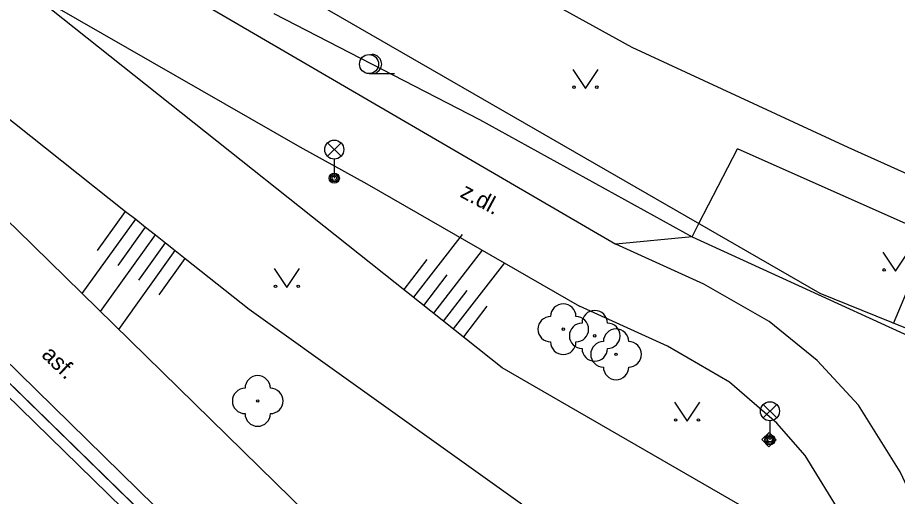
# Model space of a CAD drawing. Extents: x -598932 to -598196, y -1162207 to -1161504.
# Drawn here: x -598623.8 to -598589.11, y -1162050.68 to -1162031.8 of the extents above; entities that cross this region are included whole.
import ezdxf

# ---------------------------------------------------------------- set-up
doc = ezdxf.new("R2010")
doc.units = 0
for name, color, linetype in [('Level 22', 7, 'Continuous'), ('Level 33', 7, 'Continuous'), ('Level 36', 7, 'Continuous'), ('specificka linie pasportu komunikaci', 7, 'Continuous'), ('TM - chodniky - VP', 7, 'Continuous'), ('TM - hladina vodniho toku_ bazenu_ nadrze', 7, 'Continuous'), ('TM - horni hrana svahu', 7, 'Continuous'), ('TM - popis povrchu', 7, 'Continuous'), ('TM - rozhrani ploch obecne - VP', 7, 'Continuous'), ('TM - srafovani', 7, 'Continuous'), ('TM - zabradli - VP', 7, 'Continuous')]:
    doc.layers.add(name, color=color, linetype=linetype)

msp = doc.modelspace()

# ---------------------------------------------------------------- linework, layer by layer
at = {"layer": 'Level 22'}
for centre in [(-598602.28, -1162044.09), (-598601.04, -1162044.35), (-598600.2, -1162045.08), (-598614.33, -1162046.92)]:
    msp.add_circle(centre, 0.05, dxfattribs=at)
for centre, start, end in [((-598602.28, -1162043.59), 0, 180), ((-598601.04, -1162043.85), 0, 180), ((-598602.78, -1162044.09), 90, 270), ((-598601.78, -1162044.09), 270, 90), ((-598601.54, -1162044.35), 90, 270), ((-598600.2, -1162044.58), 0, 180), ((-598600.54, -1162044.35), 270, 90), ((-598602.28, -1162044.59), 180, 0), ((-598600.7, -1162045.08), 90, 270), ((-598599.7, -1162045.08), 270, 90), ((-598601.04, -1162044.85), 180, 0), ((-598600.2, -1162045.58), 180, 0), ((-598614.33, -1162046.42), 0, 180), ((-598614.83, -1162046.92), 90, 270), ((-598613.83, -1162046.92), 270, 90), ((-598614.33, -1162047.42), 180, 0)]:
    msp.add_arc(centre, 0.5, start, end, dxfattribs=at)
at = {"layer": 'Level 33'}
for p, q in [((-598611.575, -1162037.27), (-598611.045, -1162036.74)), ((-598611.575, -1162036.74), (-598611.045, -1162037.27)), ((-598611.31, -1162037.38), (-598611.31, -1162038.13)), ((-598594.395, -1162047.59), (-598593.865, -1162047.06)), ((-598594.395, -1162047.06), (-598593.865, -1162047.59)), ((-598594.13, -1162047.7), (-598594.13, -1162048.45))]:
    msp.add_line(p, q, dxfattribs=at)
for centre, radius in [((-598611.31, -1162037.005), 0.375), ((-598611.31, -1162038.13), 0.2), ((-598611.31, -1162038.13), 0.145), ((-598611.31, -1162038.13), 0.0876), ((-598594.13, -1162047.325), 0.375), ((-598594.13, -1162048.45), 0.2), ((-598594.13, -1162048.45), 0.145), ((-598594.13, -1162048.45), 0.0876)]:
    msp.add_circle(centre, radius, dxfattribs=at)
at = {"layer": 'Level 36'}
msp.add_line((-598609.94, -1162034.005), (-598608.94, -1162034.005), dxfattribs=at)
for points in [[(-598601.91, -1162033.84), (-598601.41, -1162034.59), (-598600.91, -1162033.84)], [(-598589.68, -1162041.05), (-598589.18, -1162041.8), (-598588.68, -1162041.05)], [(-598613.68, -1162041.7), (-598613.18, -1162042.45), (-598612.68, -1162041.7)], [(-598597.9, -1162046.97), (-598597.4, -1162047.72), (-598596.9, -1162046.97)]]:
    msp.add_lwpolyline(points, dxfattribs=at)
for centre, radius in [((-598609.94, -1162033.63), 0.375), ((-598601.86, -1162034.54), 0.05), ((-598600.961, -1162034.54), 0.05), ((-598589.63, -1162041.75), 0.05), ((-598613.63, -1162042.4), 0.05), ((-598612.731, -1162042.4), 0.05), ((-598597.85, -1162047.67), 0.05), ((-598596.951, -1162047.67), 0.05)]:
    msp.add_circle(centre, radius, dxfattribs=at)
msp.add_arc((-598609.815, -1162033.63), 0.375, 260.4059, 99.5941, dxfattribs=at)
at = {"layer": 'specificka linie pasportu komunikaci'}
for points in [[(-598613.699, -1162031.635), (-598613.693, -1162031.639), (-598605.587, -1162035.812), (-598597.2, -1162040.447)], [(-598598.18, -1162071.56), (-598600.34, -1162069.418), (-598614.157, -1162055.953), (-598633.82, -1162036.75)], [(-598597.2, -1162040.447), (-598596.929, -1162039.92), (-598595.41, -1162036.97)], [(-598597.2, -1162040.447), (-598600.21, -1162040.73)], [(-598597.2, -1162040.447), (-598584.327, -1162046.336), (-598582.19, -1162047.02)]]:
    msp.add_lwpolyline(points, dxfattribs=at)
at = {"layer": 'TM - chodniky - VP'}
for points in [[(-598623.42, -1162030.71), (-598612.67, -1162036.89), (-598610.02, -1162038.35), (-598601.64, -1162043.18)], [(-598616.47, -1162031.26), (-598616.42, -1162031.29), (-598600.21, -1162040.73)], [(-598630.72, -1162033.53), (-598623.82, -1162040.17), (-598610.46, -1162053.25), (-598599.79, -1162063.71), (-598596.691, -1162066.802), (-598596.064, -1162067.426), (-598595.889, -1162067.601), (-598595.77, -1162067.72), (-598595.19, -1162067.952), (-598592.82, -1162068.9)], [(-598633.81, -1162036.07), (-598633.47, -1162036.4), (-598626.42, -1162043.21), (-598613.03, -1162056.32), (-598598.06, -1162071.1)], [(-598596.74, -1162042.31), (-598600.21, -1162040.73)], [(-598589.23, -1162070.22), (-598587.03, -1162064.32), (-598586.49, -1162062.18), (-598586.29, -1162059.72), (-598586.64, -1162056.69), (-598586.88, -1162055.536), (-598587.07, -1162054.62), (-598587.91, -1162052.04), (-598588.99, -1162049.71), (-598590.64, -1162047.09), (-598592.27, -1162045.32), (-598594.16, -1162043.79), (-598596.74, -1162042.31)], [(-598589.65, -1162062.75), (-598589.31, -1162061.21), (-598589.19, -1162059.52), (-598589.47, -1162057.27), (-598589.69, -1162056.13), (-598589.83, -1162055.37), (-598590.47, -1162053.3), (-598591.26, -1162051.49), (-598592.74, -1162049.07), (-598593.86, -1162047.79), (-598595.73, -1162046.18), (-598598.17, -1162044.76), (-598601.64, -1162043.18)], [(-598594.45, -1162048.44), (-598594.16, -1162048.16), (-598593.89, -1162048.45), (-598594.18, -1162048.73), (-598594.45, -1162048.44)]]:
    msp.add_lwpolyline(points, dxfattribs=at)
at = {"layer": 'TM - hladina vodniho toku_ bazenu_ nadrze'}
msp.add_lwpolyline([(-598579.96, -1162041.91), (-598591.05, -1162036.92), (-598599.56, -1162032.98), (-598612.76, -1162025.69), (-598613.24, -1162025.43)], dxfattribs=at)
at = {"layer": 'TM - horni hrana svahu'}
for points in [[(-598615.37, -1162029.27), (-598614.88, -1162029.57), (-598613.499, -1162030.366), (-598592.16, -1162042.67)], [(-598594.46, -1162051.52), (-598604.69, -1162045.61), (-598623.42, -1162030.71)], [(-598628.96, -1162031.96), (-598619.54, -1162039.44), (-598619.14, -1162039.75), (-598618.76, -1162040.06), (-598618.36, -1162040.37), (-598617.97, -1162040.68), (-598617.58, -1162040.99), (-598617.19, -1162041.3), (-598614.67, -1162043.3), (-598601.81, -1162052.49)], [(-598592.16, -1162042.67), (-598582.1, -1162046.75)]]:
    msp.add_lwpolyline(points, dxfattribs=at)
at = {"layer": 'TM - rozhrani ploch obecne - VP'}
for points in [[(-598599.69, -1162070.69), (-598614.45, -1162056.23), (-598634.11, -1162037.04), (-598633.82, -1162036.75)], [(-598580.93, -1162043.42), (-598595.41, -1162036.97)]]:
    msp.add_lwpolyline(points, dxfattribs=at)
at = {"layer": 'TM - srafovani'}
for points in [[(-598620.65, -1162040.99), (-598619.54, -1162039.44)], [(-598621.25, -1162042.68), (-598619.14, -1162039.75)], [(-598619.83, -1162041.57), (-598618.76, -1162040.06)], [(-598620.53, -1162043.39), (-598618.36, -1162040.37)], [(-598606.27, -1162040.35), (-598608.18, -1162042.83)], [(-598619.8, -1162044.1), (-598617.58, -1162040.99)], [(-598619.02, -1162042.15), (-598617.97, -1162040.68)], [(-598605.48, -1162040.97), (-598607.4, -1162043.45)], [(-598618.21, -1162042.73), (-598617.19, -1162041.3)], [(-598607.66, -1162041.34), (-598608.57, -1162042.52)], [(-598604.6, -1162041.47), (-598606.62, -1162044.08)], [(-598606.87, -1162041.95), (-598607.79, -1162043.15)], [(-598589.26, -1162043.87), (-598588.63, -1162042.36)], [(-598606.08, -1162042.56), (-598607.01, -1162043.77)], [(-598605.29, -1162043.18), (-598606.22, -1162044.39)]]:
    msp.add_lwpolyline(points, dxfattribs=at)
at = {"layer": 'TM - zabradli - VP'}
msp.add_lwpolyline([(-598633.82, -1162036.75), (-598614.17, -1162055.95), (-598599.48, -1162070.6)], dxfattribs=at)

# ---------------------------------------------------------------- texts
at = {"layer": 'TM - popis povrchu'}
for s, rotation, p in [('z.dl.', 331.88, (-598606.39, -1162038.85)), ('asf.', 316, (-598622.89, -1162045.14))]:
    msp.add_text(s, height=0.65, rotation=rotation, dxfattribs=at).set_placement(p)

doc.saveas('drawing.dxf')
